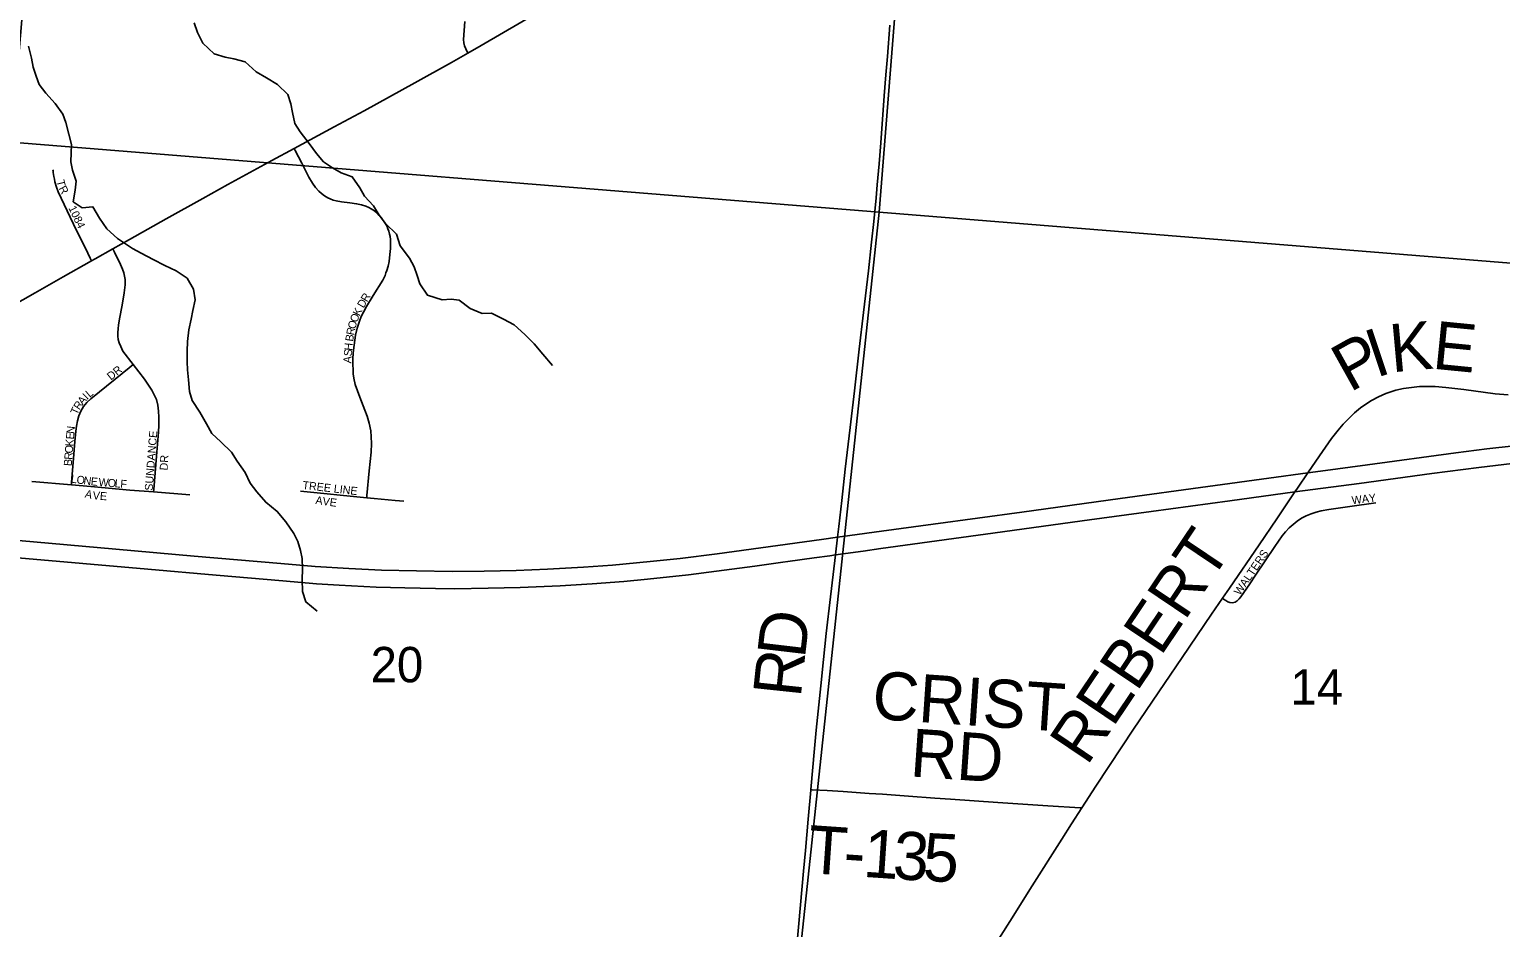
# Model space of a CAD drawing. Extents: x 1410790 to 1770854, y 566777 to 831614.
# Drawn here: x 1576682 to 1585877, y 690045 to 695655 of the extents above; entities that cross this region are included whole.
import ezdxf

# ---------------------------------------------------------------- set-up
doc = ezdxf.new("R2010")
doc.units = 0
for name, color, linetype in [('GM_X_County_Road', 7, 'Continuous'), ('GM_X_County_Road_Text', 7, 'Continuous'), ('GM_X_Interstate_Route', 7, 'Continuous'), ('GM_X_Minor_River', 7, 'Continuous'), ('GM_X_Section', 7, 'Continuous'), ('GM_X_Section_Text', 7, 'Continuous'), ('GM_X_Township_Road', 7, 'Continuous'), ('GM_X_Township_Road_Text', 7, 'Continuous'), ('GM_X_Township_Subdivision', 7, 'Continuous'), ('GM_X_Township_Subdivision_Text', 7, 'Continuous')]:
    doc.layers.add(name, color=color, linetype=linetype)

msp = doc.modelspace()

# ---------------------------------------------------------------- linework, layer by layer
at = {"layer": 'GM_X_County_Road'}
for points in [[(1579422.6, 695507), (1579505.5, 695554.3), (1579874.9, 695767.9), (1579996, 695837.7)], [(1578336.2, 694911.2), (1578586.7, 695046.3), (1578774.5, 695147.3), (1579091.3, 695320.4), (1579320.3, 695448.7), (1579422.6, 695507)], [(1577202.8, 694283.5), (1577307.3, 694342.3), (1577536.2, 694470.8), (1577765.3, 694599), (1577923.2, 694686.4), (1578196.8, 694835.9), (1578336.2, 694911.2)], [(1577071, 694209.3), (1577092.7, 694221.6), (1577202.8, 694283.5)], [(1576718.1, 694010), (1576892.7, 694108.7), (1577071, 694209.3)], [(1574780, 692914.2), (1574926, 692999.1), (1575188.7, 693144.6), (1575362.1, 693242), (1575585.2, 693368.9), (1575853.5, 693521.1), (1576718.1, 694010)], [(1584528.1, 692672.8), (1584591.1, 692765.5), (1584607, 692788.8), (1584672.7, 692884.9), (1584745.9, 692992), (1584820.7, 693100.1), (1584861, 693152.2), (1584893.3, 693189.6), (1584927.5, 693225.3), (1584963.6, 693259.2), (1585001.6, 693291), (1585028.2, 693310.6), (1585070.3, 693336.9), (1585114.1, 693360.1), (1585159.5, 693380), (1585190.6, 693391.2), (1585222.3, 693400.6), (1585270.7, 693411.4), (1585319.7, 693418.9), (1585369, 693423.7), (1585418.5, 693425.4), (1585467.9, 693424.2), (1585533.6, 693419.2), (1585647.8, 693405.3), (1585843, 693379.4), (1585924.4, 693371.4)], [(1584138.4, 692101.4), (1584182, 692165.2), (1584367.1, 692436.1), (1584477.8, 692598.8), (1584528.1, 692672.8)], [(1583259.4, 690791.9), (1583347, 690927.4), (1583428.4, 691050.6), (1583509.4, 691174.1), (1583582.3, 691283.2), (1583775.2, 691568.9), (1583886.9, 691730.9), (1584070.9, 692002.7), (1584138.4, 692101.4)], [(1582372.6, 689269.5), (1582385, 689308.6), (1582420.9, 689417.8), (1582443.8, 689479.6), (1582463.8, 689524.9), (1582486.4, 689568.8), (1582519.8, 689625.6), (1582598.6, 689750.6), (1582687.1, 689888.7), (1582809.9, 690082.8), (1582949.8, 690305), (1583133.7, 690596.4), (1583195.6, 690693.2), (1583259.4, 690791.9)]]:
    msp.add_lwpolyline(points, dxfattribs=at)
at = {"layer": 'GM_X_Interstate_Route'}
for points in [[(1576614.9, 692462.4), (1577223.3, 692408.3), (1577712.3, 692365.2), (1578252.7, 692318.4), (1578467.4, 692300.9), (1578678.5, 692287.2), (1578883.1, 692278), (1579101.5, 692272.5), (1579325.4, 692269.7), (1579523.5, 692270.7), (1579723.6, 692275.3), (1579919.9, 692283.5), (1580145.7, 692296.4), (1580327.4, 692309.2), (1580562.2, 692331.2), (1580750.3, 692350.5), (1580980.6, 692379.8), (1581633, 692469.8), (1581732.4, 692483.2), (1581810.1, 692493.6), (1582007.4, 692521.2), (1582329.4, 692564.3), (1582884.6, 692640.4), (1583498.4, 692725.8), (1584046.2, 692800.1), (1584427.9, 692852.4), (1584672.7, 692884.9), (1584751.3, 692895.3), (1585044.5, 692935.9), (1585596.4, 693010), (1585791.6, 693034.6), (1586150.2, 693074.4)], [(1581892.8, 692396.4), (1582002.6, 692411.7), (1582658, 692501.6), (1583306.9, 692591.4), (1583693.7, 692643.2), (1584184.2, 692710.9), (1584591.1, 692765.5), (1584992, 692819.3), (1585447.2, 692880.1), (1585739.9, 692918.3), (1586000.6, 692949.3), (1586277.8, 692979.3), (1586689.1, 693020.5), (1586835.3, 693032.9), (1586975.6, 693044.8), (1587190.6, 693060.7), (1587363.5, 693073.4), (1587536.8, 693085), (1587835.9, 693100.8), (1588132.6, 693113.9)], [(1576609.1, 692353.6), (1577422.9, 692282.8), (1577848.8, 692245.8), (1578265.3, 692209.8), (1578476.7, 692192.9), (1578618.3, 692183.4), (1578849.8, 692171.8), (1579029.5, 692166.5), (1579220.8, 692163.3), (1579339.2, 692161.2), (1579548.4, 692164.4), (1579749.2, 692169.7), (1579998.7, 692179.2), (1580199.5, 692191.9), (1580398.2, 692206.7), (1580545.1, 692221.5), (1580802, 692248.9), (1580976.4, 692270.1), (1581215.2, 692302.8), (1581390.7, 692327.2), (1581422.1, 692331.4)], [(1581422.1, 692331.4), (1581586.2, 692353.6), (1581683.7, 692367.2)], [(1581683.7, 692367.2), (1581719.2, 692372.2), (1581892.8, 692396.4)]]:
    msp.add_lwpolyline(points, dxfattribs=at)
at = {"layer": 'GM_X_Minor_River'}
for points in [[(1577712.8, 695695.7), (1577732.1, 695635.3), (1577765.3, 695568.8), (1577836.7, 695501.8), (1577904.7, 695481), (1577960.7, 695470.3), (1578030.6, 695451.4), (1578100.1, 695390.5), (1578163.8, 695351.6), (1578233.5, 695310.7), (1578296.9, 695247.8), (1578316.2, 695189.5), (1578325.6, 695135.2), (1578340.8, 695066.9), (1578374.2, 695014.4), (1578431.5, 694941.5), (1578476.9, 694878.9), (1578520.4, 694828.2), (1578576, 694789.5), (1578629.8, 694758.8), (1578699.7, 694733.9), (1578747, 694665.2), (1578776.4, 694612.8), (1578831.8, 694552), (1578867.2, 694495.4), (1578908.7, 694442.8), (1578976.1, 694375.9), (1578999.2, 694303.4), (1579058.5, 694226.6), (1579087.9, 694172.1), (1579105.3, 694117.8), (1579122.7, 694065.4), (1579169.9, 693994.7), (1579261.8, 693965.6), (1579318.1, 693970.9), (1579368.1, 693964.3), (1579437.7, 693911.4), (1579511.5, 693880.5), (1579569.7, 693881.8), (1579645.4, 693844.8), (1579711.2, 693810), (1579778.6, 693749), (1579836.1, 693690.2), (1579891.4, 693625.4), (1579950.7, 693556.6)], [(1576676.1, 695549.5), (1576695.2, 695475.1), (1576706.5, 695418.8), (1576723.9, 695362.5), (1576743.3, 695310.2), (1576784.8, 695257.5), (1576844.2, 695192.7), (1576891.5, 695126), (1576908.9, 695073.7), (1576928, 695001.3), (1576945.3, 694936.9), (1576942.6, 694884.8), (1576942, 694828.7), (1576951.3, 694776.5), (1576974.6, 694708), (1576967.8, 694650), (1576954.9, 694578), (1577012.6, 694541.2), (1577078.9, 694546.4), (1577120.1, 694475.8), (1577165.4, 694409.1), (1577232.9, 694348.2), (1577326.4, 694287), (1577380.2, 694256.3), (1577455.9, 694217.3), (1577529.6, 694180.3), (1577599.4, 694147.4), (1577669, 694100.5), (1577708.3, 694031.9), (1577717.5, 693965.7), (1577702.7, 693899.7), (1577694, 693845.6), (1577679.1, 693777.7), (1577670.2, 693705.6), (1577667.4, 693645.5), (1577668.6, 693579.3), (1577670, 693529.2), (1577677.3, 693467), (1577682.4, 693392.7), (1577699.7, 693336.4), (1577747, 693263.7), (1577788.2, 693191), (1577821.6, 693130.5), (1577879.1, 693079.7), (1577944.5, 693014.8), (1577979.9, 692958.2), (1578031.2, 692887.5), (1578062.4, 692821), (1578103.9, 692766.4), (1578159.2, 692701.6), (1578230.7, 692644.6), (1578284.1, 692579.8), (1578335.3, 692507.1), (1578358.8, 692456.7), (1578376.1, 692400.3), (1578387.6, 692350.1), (1578388.8, 692283.9), (1578386, 692219.8), (1578389, 692143.6), (1578410.3, 692079.2), (1578479.8, 692022.2)]]:
    msp.add_lwpolyline(points, dxfattribs=at)
at = {"layer": 'GM_X_Section'}
for points in [[(1577021.1, 700282.3), (1582419.4, 699882.5), (1581992.1, 694512.5), (1576570.4, 694950.7)], [(1582419.4, 699882.5), (1587775.4, 699456.9), (1587281.6, 694087.3), (1581992.1, 694512.5)], [(1576570.4, 694950.7), (1581992.1, 694512.5), (1581423.5, 689188.8), (1576099.9, 689633.4)], [(1581992.1, 694512.5), (1587281.6, 694087.3), (1586796.8, 688787.6), (1581423.5, 689188.8)]]:
    msp.add_lwpolyline(points, close=True, dxfattribs=at)
at = {"layer": 'GM_X_Township_Road'}
for points in [[(1581566.5, 690906.3), (1581589.1, 691163.9), (1581599.1, 691278.3), (1581627.5, 691555.7), (1581644.9, 691718.8), (1581662.7, 691881.9), (1581689.6, 692109.8), (1581715.2, 692338.1), (1581719.2, 692372.2), (1581732.4, 692483.2), (1581740.2, 692549.9), (1581758.9, 692712.8), (1581781.5, 692908.3), (1581812, 693168.8), (1581838.6, 693396.8), (1581868, 693657.6), (1581894.8, 693885.7), (1581925.7, 694146.3), (1581945.8, 694325.5), (1581960.3, 694455.9), (1581974, 694602.7), (1581981.1, 694684.4), (1581992.5, 694815), (1582003.1, 694945.8), (1582024.4, 695240.2), (1582034.9, 695370.9), (1582044.1, 695485.4), (1582060.3, 695681.5)], [(1581454.6, 689672), (1581456.4, 689694.1), (1581468.8, 689824.7), (1581480.4, 689955.4), (1581490.7, 690069.7), (1581520.7, 690396.2), (1581532.4, 690526.8), (1581550.1, 690722.8), (1581566.1, 690902.5), (1581566.5, 690906.3)], [(1581566.5, 690906.3), (1581574.2, 690905.9), (1581668.8, 690900.9), (1581767, 690894.1), (1581849, 690888.4), (1581931, 690883), (1582013, 690877.5), (1582177, 690865.7), (1582341, 690853.9), (1582439.4, 690846.6), (1582734.4, 690825.3), (1583046.1, 690805.7), (1583249.3, 690792.5), (1583259.4, 690791.9)]]:
    msp.add_lwpolyline(points, dxfattribs=at)
at = {"layer": 'GM_X_Township_Subdivision'}
for points in [[(1579422.6, 695507), (1579420.9, 695510.8), (1579410.5, 695532.5), (1579402.2, 695551.7), (1579397, 695571.3), (1579395, 695592), (1579402.5, 695704.1)], [(1578790.3, 692729.3), (1578791.6, 692743.2), (1578806, 692897.5), (1578817.5, 693014.5), (1578821.1, 693068.3), (1578818.9, 693109.2), (1578815.3, 693148), (1578805.3, 693194.7), (1578792.3, 693239.2), (1578779.4, 693277.2), (1578747.1, 693358.3), (1578732, 693396.4), (1578718.4, 693437.3), (1578709.8, 693476.1), (1578706.2, 693504.1), (1578704.8, 693524.9), (1578702.6, 693566.5), (1578702.6, 693594.5), (1578706.2, 693635.4), (1578711.2, 693683.5), (1578719.8, 693744.5), (1578729.9, 693788.3), (1578744.3, 693833.5), (1578756.5, 693860.8), (1578769.4, 693889.5), (1578788.7, 693924), (1578831.1, 693992.9), (1578890.7, 694089.1), (1578905.8, 694118.5), (1578910.8, 694133.6), (1578916.5, 694149.4), (1578923.7, 694176.7), (1578930.2, 694206.1), (1578935.2, 694248.4), (1578938, 694287.2), (1578939.5, 694313), (1578938, 694341.8), (1578935.9, 694360.4), (1578932.3, 694376.2), (1578928, 694394.1), (1578923, 694408.5), (1578917.2, 694423.6), (1578908.6, 694440.1), (1578900, 694453.7), (1578890, 694468.1), (1578880.6, 694479.6), (1578868.4, 694493.2), (1578856.2, 694506.8), (1578838.3, 694521.9), (1578818.2, 694534.1), (1578803.8, 694542.7), (1578785.2, 694550.6), (1578758.6, 694559.2), (1578727, 694565.7), (1578683.9, 694572.2), (1578632.3, 694577.9), (1578600, 694583.7), (1578581.3, 694588.7), (1578562.6, 694595.9), (1578546.8, 694603), (1578527.5, 694614.5), (1578508.1, 694628.9), (1578490.9, 694644.7), (1578470, 694666.9), (1578452.1, 694693.5), (1578429.1, 694732.2), (1578383.9, 694818.4), (1578342.3, 694899.5), (1578336.2, 694911.2)], [(1577071, 694209.3), (1577062.5, 694226.5), (1577032, 694288.3), (1576977.4, 694399.5), (1576917.3, 694521.4), (1576862.6, 694639.8), (1576850.9, 694668.5), (1576841.5, 694702.9), (1576838.1, 694719.7), (1576835.2, 694735.1), (1576832.9, 694749), (1576831.2, 694760.9), (1576830.1, 694771.1), (1576829.6, 694777.7)], [(1577331.5, 693561.6), (1577267, 693645.4), (1577253.5, 693673.3), (1577243.7, 693697.4), (1577237.4, 693719), (1577234.7, 693739.6), (1577234.7, 693759.3), (1577236.5, 693786.2), (1577238.3, 693806.8), (1577245.5, 693846.3), (1577261.6, 693931.5), (1577275, 694008.6), (1577280.4, 694059.7), (1577280.4, 694092), (1577276.8, 694113.5), (1577272.3, 694134.1), (1577264.3, 694157.4), (1577252.6, 694186.1), (1577213.2, 694263.2), (1577202.8, 694283.5)], [(1576944.7, 692809.8), (1576946, 692826.8), (1576954.8, 692950.2), (1576966.9, 693080.1), (1576972.4, 693145.2), (1576976.5, 693177.5), (1576982.6, 693209.6), (1576991.3, 693241), (1576997.2, 693256.3), (1577004.2, 693271), (1577012.3, 693285.1), (1577021.3, 693298.7), (1577041.9, 693324), (1577065.3, 693346.7), (1577218.1, 693469.3), (1577306.7, 693541.4), (1577331.5, 693561.6)], [(1577457.5, 692765.6), (1577458.9, 692781.1), (1577476.8, 692989.1), (1577489.3, 693139.8), (1577490.2, 693181.9), (1577492, 693232.1), (1577489.3, 693269.7), (1577484, 693308.3), (1577475.9, 693342.4), (1577465.1, 693368.4), (1577448.1, 693402.5), (1577427.5, 693433.8), (1577401.5, 693470.6), (1577331.5, 693561.6)], [(1576697.6, 692831.3), (1576944.7, 692809.8)], [(1576944.7, 692809.8), (1577065.5, 692799.3), (1577310.1, 692777.6), (1577457.5, 692765.6)], [(1577457.5, 692765.6), (1577685.3, 692747)], [(1578375.8, 692771.3), (1578790.3, 692729.3)], [(1578790.3, 692729.3), (1578836.1, 692724.7), (1578967.6, 692711.7), (1579021.3, 692707.3)], [(1584138.4, 692101.4), (1584145.5, 692096.6), (1584158.8, 692087.4), (1584172.5, 692079.2), (1584185.5, 692074.9), (1584201.9, 692073.9), (1584217.7, 692077.7), (1584231.2, 692086.5), (1584242.9, 692098), (1584253.2, 692110.7), (1584272.4, 692137.1), (1584309.4, 692191.6), (1584345.8, 692246.7), (1584464.9, 692424.1), (1584512.4, 692491.2), (1584532.8, 692516.9), (1584555.2, 692541), (1584579.4, 692563.3), (1584605.3, 692583.5), (1584633, 692601.1), (1584662.2, 692616.3), (1584692.3, 692629.5), (1584723.3, 692640.3), (1584755.2, 692648.4), (1584803.7, 692657.2), (1584933.9, 692675.2), (1585096.8, 692697.4)]]:
    msp.add_lwpolyline(points, dxfattribs=at)

# ---------------------------------------------------------------- texts
at = {"layer": 'GM_X_County_Road_Text'}
for s, rotation, p in [('K', 5.19624, (1585196.8, 693512.6)), ('E', 354.3619, (1585444.7, 693536.5)), ('P', 29.13698, (1584934.6, 693384.7)), ('I', 18.44976, (1585097.9, 693477.3)), ('REBERT', 56.06377, (1583291.5, 691049.6))]:
    msp.add_text(s, height=300, rotation=rotation, dxfattribs=at).set_placement(p)
at = {"layer": 'GM_X_Section_Text'}
for s, p in [('20', (1578814.8, 691576.9)), ('14', (1584563.4, 691437.7))]:
    msp.add_text(s, height=221, rotation=0.00001, dxfattribs=at).set_placement(p)
at = {"layer": 'GM_X_Township_Road_Text'}
for s, rotation, p in [('D', 83.30399, (1581528.2, 691720.8)), ('R', 83.97832, (1581502.4, 691476.7)), ('CRIST', 356.12105, (1581943.6, 691349.3)), ('RD', 356.05424, (1582181, 690989.4)), ('T', 356.05636, (1581539.9, 690386.1)), ('1', 356.12344, (1581887.1, 690362.2)), ('3', 356.31673, (1582072.6, 690349.6)), ('5', 357.14856, (1582261.7, 690337.5)), ('-', 356.07002, (1581763.9, 690370.7))]:
    msp.add_text(s, height=300, rotation=rotation, dxfattribs=at).set_placement(p)
at = {"layer": 'GM_X_Township_Subdivision_Text'}
for s, rotation, p in [('T', 283.93355, (1576851, 694708.4)), ('R', 297.24678, (1576863.9, 694662.6)), ('1084', 295.64329, (1576924.5, 694539.6)), ('R', 59.61942, (1578792.6, 693948.6)), ('K', 63.48871, (1578744.7, 693860.5)), ('D', 59.81593, (1578770.5, 693910.6)), ('R', 78.9044, (1578710.6, 693741.6)), ('O', 74.21672, (1578717.9, 693779.4)), ('O', 69.12803, (1578729.5, 693820.6)), ('B', 81.83727, (1578705, 693703)), ('A', 85.42694, (1578693.2, 693568)), ('S', 85.40537, (1578696.7, 693611.9)), ('H', 84.83524, (1578699.5, 693646.8)), ('DR', 38.66602, (1577191.9, 693460.5)), ('R', 56.18195, (1576994.8, 693273.9)), ('A', 49.65711, (1577015.9, 693305.6)), ('I', 44.24269, (1577043.6, 693338.2)), ('L', 39.72861, (1577058.6, 693352.9)), ('T', 65.97093, (1576981.6, 693243.7)), ('N', 84.17632, (1576962.8, 693127.4)), ('O', 85.34724, (1576952.8, 693004.8)), ('K', 85.3398, (1576956.4, 693048.7)), ('E', 85.34898, (1576959.9, 693092.5)), ('SUNDANCE', 85.48563, (1577452.4, 692771.9)), ('B', 85.35635, (1576946.4, 692925.9)), ('R', 85.34772, (1576949.6, 692965.4)), ('DR', 86.98872, (1577546.1, 692899.2)), ('L', 352.19055, (1576939.5, 692824.5)), ('O', 352.19086, (1576974.4, 692819.7)), ('N', 352.51908, (1577018.3, 692813.7)), ('E', 354.62983, (1577063.9, 692807.7)), ('W', 355.52084, (1577112.9, 692803.3)), ('O', 355.51411, (1577170, 692798.8)), ('L', 355.5154, (1577213.8, 692795.4)), ('F', 355.5154, (1577248.9, 692792.6)), ('TREE LINE', 353.48064, (1578386.8, 692784.9)), ('A', 346.30832, (1577025.5, 692732.4)), ('V', 354.96973, (1577076.4, 692720.6)), ('E', 355.65153, (1577120.9, 692716.7)), ('AVE', 352.14337, (1578467.7, 692690.9)), ('WAY', 6.91053, (1584949.4, 692688.1)), ('WALTERS', 55.8383, (1584247.5, 692116.3))]:
    msp.add_text(s, height=50, rotation=rotation, dxfattribs=at).set_placement(p)

doc.saveas('drawing.dxf')
